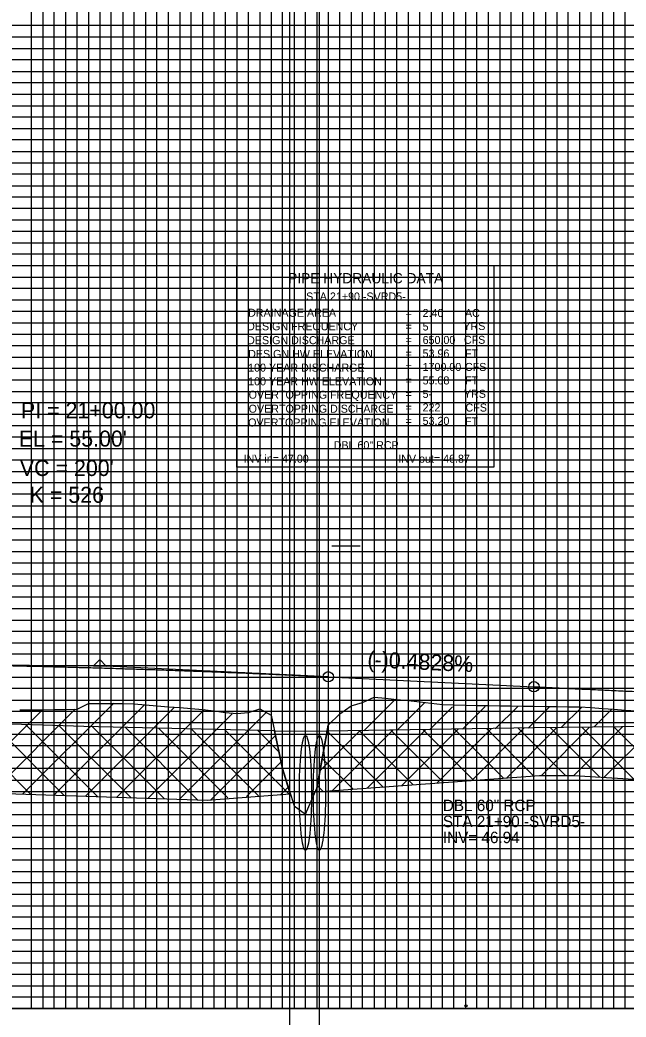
# Model space of a CAD drawing. Extents: x 2345490 to 2445302, y 465165 to 573888.
# Drawn here: x 2382805.1 to 2383070.5, y 491499.3 to 491935.5 of the extents above; entities that cross this region are included whole.
import ezdxf

# ---------------------------------------------------------------- set-up
doc = ezdxf.new("R2010")
doc.units = 0
for name, color, linetype in [('Default', 7, 'Continuous'), ('Old_Level_1', 7, 'Continuous'), ('Old_Level_2', 7, 'Continuous'), ('Old_Level_3', 7, 'Continuous'), ('Old_Level_4', 7, 'Continuous'), ('Old_Level_41', 7, 'Continuous'), ('Old_Level_42', 7, 'Continuous'), ('Old_Level_43', 7, 'Continuous'), ('Old_Level_5', 7, 'Continuous'), ('Old_Level_50', 7, 'Continuous'), ('Old_Level_51', 7, 'Continuous'), ('Old_Level_63', 7, 'Continuous'), ('Prop Vertical Profile Grade', 7, 'Continuous')]:
    doc.layers.add(name, color=color, linetype=linetype)

msp = doc.modelspace()

# ---------------------------------------------------------------- linework, layer by layer
at = {"layer": 'Default'}
msp.add_line((2382916.56515, 491624.43941), (2382939.67785, 491624.39117), dxfattribs=at)
at = {"layer": 'Old_Level_1'}
msp.add_lwpolyline([(2382805.125, 491633.6205), (2382810.125, 491633.6725), (2382815.125, 491633.7245), (2382820.125, 491633.7765), (2382825.125, 491633.8285), (2382830.125, 491633.921), (2382835.125, 491636.42125), (2382840.125, 491636.41825), (2382845.125, 491636.4155), (2382850.125, 491636.4125), (2382855.125, 491636.221), (2382860.125, 491635.8305), (2382865.125, 491635.44025), (2382870.125, 491635.05), (2382875.125, 491634.6595), (2382880.125, 491634.26925), (2382885.125, 491633.879), (2382890.125, 491633.209), (2382895.125, 491632.52625), (2382900.125, 491632.04225), (2382905.125, 491632.4315), (2382910.125, 491634.164), (2382915.125, 491631.2635), (2382920.125, 491608.03925), (2382925.125, 491591.604), (2382930.125, 491588.09825), (2382935.125, 491599.454), (2382940.125, 491626.98825), (2382945.125, 491631.9855), (2382950.125, 491635.42325), (2382955.125, 491636.93325), (2382960.125, 491639.27975), (2382965.125, 491638.7695), (2382970.125, 491638.22925), (2382975.125, 491637.68925), (2382980.125, 491637.149), (2382985.125, 491636.609), (2382990.125, 491636.06875), (2382995.125, 491635.8115), (2383000.125, 491635.71075), (2383005.125, 491635.63575), (2383010.125, 491635.56075), (2383015.125, 491635.48575), (2383020.125, 491635.411), (2383025.125, 491635.336), (2383030.125, 491635.261), (2383035.125, 491635.186), (2383040.125, 491635.11125), (2383045.125, 491635.03625), (2383050.125, 491634.96125), (2383055.125, 491634.6185), (2383060.125, 491634.28925), (2383065.125, 491633.92475), (2383070.125, 491633.55625), (2383075.125, 491633.1875)], dxfattribs=at)
at = {"layer": 'Old_Level_2'}
for p, q in [((2382740.125, 491653.97897), (2382837.37514, 491652.98053)), ((2382840.125, 491655.7023), (2382837.37514, 491652.98053)), ((2382837.37514, 491652.98053), (2382842.8718, 491652.8197)), ((2382842.8718, 491652.8197), (2382840.125, 491655.7023)), ((2382940.125, 491648.12471), (2382842.8718, 491652.8197)), ((2383030.125, 491643.77989), (2383127.3782, 491639.0849))]:
    msp.add_line(p, q, dxfattribs=at)
for centre in [(2382940.125, 491648.12471), (2383030.125, 491643.77989)]:
    msp.add_circle(centre, 2.25, dxfattribs=at)
at = {"layer": 'Old_Level_3'}
msp.add_circle((2383000.34952, 491504.17888), 0.5, dxfattribs=at)
for centre in [(2382930.125, 491597.35225), (2382936.22982, 491597.35225)]:
    msp.add_ellipse(centre, major_axis=(0, 25), ratio=0.106994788, dxfattribs=at)
at = {"layer": 'Old_Level_4'}
for p, q in [((2382900.1285, 491828.06375), (2383012.6285, 491828.06375)), ((2382900.1285, 491753.06375), (2382900.1285, 491828.06375)), ((2383012.6285, 491828.06375), (2383012.6285, 491753.06375)), ((2383012.6285, 491753.06375), (2382900.1285, 491753.06375))]:
    msp.add_line(p, q, dxfattribs=at)
msp.add_lwpolyline([(2382900.1285, 491753.06375), (2383012.6285, 491753.06375), (2383012.6285, 491739.84875), (2382900.1285, 491739.84875)], close=True, dxfattribs=at)
at = {"layer": 'Old_Level_41'}
for p, q in [((2382941.625, 491705.45225), (2382954.125, 491705.45225)), ((2383190.125, 491502.95225), (2381690.125, 491502.95225))]:
    msp.add_line(p, q, dxfattribs=at)
for points in [[(2382815.125, 492527.95225), (2382815.125, 491502.95225), (2382865.125, 491502.95225), (2382865.125, 492527.95225)], [(2382840.125, 492527.95225), (2382840.125, 491502.95225), (2382890.125, 491502.95225), (2382890.125, 492527.95225)], [(2382915.125, 492527.95225), (2382915.125, 491502.95225), (2382965.125, 491502.95225), (2382965.125, 492527.95225)], [(2382940.125, 492527.95225), (2382940.125, 491502.95225), (2382990.125, 491502.95225), (2382990.125, 492527.95225)], [(2383015.125, 492390.40225), (2383015.125, 491502.95225), (2383065.125, 491502.95225), (2383065.125, 492390.40225)], [(2383190.125, 491927.95225), (2381690.125, 491927.95225), (2381690.125, 491877.95225), (2383190.125, 491877.95225)], [(2383190.125, 491852.95225), (2381690.125, 491852.95225), (2381690.125, 491902.95225), (2383190.125, 491902.95225)], [(2383190.125, 491827.95225), (2381690.125, 491827.95225), (2381690.125, 491777.95225), (2383190.125, 491777.95225)], [(2383190.125, 491752.95225), (2381690.125, 491752.95225), (2381690.125, 491802.95225), (2383190.125, 491802.95225)], [(2383190.125, 491727.95225), (2381690.125, 491727.95225), (2381690.125, 491677.95225), (2383190.125, 491677.95225)], [(2383190.125, 491627.95225), (2381690.125, 491627.95225), (2381690.125, 491577.95225), (2383190.125, 491577.95225)], [(2383190.125, 491552.95225), (2381690.125, 491552.95225), (2381690.125, 491602.95225), (2383190.125, 491602.95225)], [(2383190.125, 491527.95225), (2381690.125, 491527.95225)]]:
    msp.add_lwpolyline(points, dxfattribs=at)
at = {"layer": 'Old_Level_42'}
for points in [[(2383040.125, 492390.40225), (2383040.125, 491502.95225), (2383090.125, 491502.95225), (2383090.125, 492390.40225)], [(2383190.125, 491652.95225), (2381690.125, 491652.95225), (2381690.125, 491702.95225), (2383190.125, 491702.95225)]]:
    msp.add_lwpolyline(points, dxfattribs=at)
at = {"layer": 'Old_Level_43'}
for points in [[(2382810.125, 492527.95225), (2382810.125, 491502.95225), (2382820.125, 491502.95225), (2382820.125, 492527.95225)], [(2382825.125, 492527.95225), (2382825.125, 491502.95225), (2382830.125, 491502.95225), (2382830.125, 492527.95225)], [(2382835.125, 492527.95225), (2382835.125, 491502.95225), (2382845.125, 491502.95225), (2382845.125, 492527.95225)], [(2382850.125, 492527.95225), (2382850.125, 491502.95225), (2382855.125, 491502.95225), (2382855.125, 492527.95225)], [(2382860.125, 492527.95225), (2382860.125, 491502.95225), (2382870.125, 491502.95225), (2382870.125, 492527.95225)], [(2382875.125, 492527.95225), (2382875.125, 491502.95225), (2382880.125, 491502.95225), (2382880.125, 492527.95225)], [(2382885.125, 492527.95225), (2382885.125, 491502.95225), (2382895.125, 491502.95225), (2382895.125, 492527.95225)], [(2382900.125, 492527.95225), (2382900.125, 491502.95225), (2382905.125, 491502.95225), (2382905.125, 492527.95225)], [(2382910.125, 492527.95225), (2382910.125, 491502.95225), (2382920.125, 491502.95225), (2382920.125, 492527.95225)], [(2382925.125, 492527.95225), (2382925.125, 491502.95225), (2382930.125, 491502.95225), (2382930.125, 492527.95225)], [(2382935.125, 492527.95225), (2382935.125, 491502.95225), (2382945.125, 491502.95225), (2382945.125, 492527.95225)], [(2382950.125, 492527.95225), (2382950.125, 491502.95225), (2382955.125, 491502.95225), (2382955.125, 492527.95225)], [(2382960.125, 492527.95225), (2382960.125, 491502.95225), (2382970.125, 491502.95225), (2382970.125, 492527.95225)], [(2382975.125, 492527.95225), (2382975.125, 491502.95225), (2382980.125, 491502.95225), (2382980.125, 492527.95225)], [(2382985.125, 492527.95225), (2382985.125, 491502.95225), (2382995.125, 491502.95225), (2382995.125, 492390.40225)], [(2383000.125, 492390.40225), (2383000.125, 491502.95225), (2383005.125, 491502.95225), (2383005.125, 492390.40225)], [(2383010.125, 492390.40225), (2383010.125, 491502.95225), (2383020.125, 491502.95225), (2383020.125, 492390.40225)], [(2383025.125, 492390.40225), (2383025.125, 491502.95225), (2383030.125, 491502.95225), (2383030.125, 492390.40225)], [(2383035.125, 492390.40225), (2383035.125, 491502.95225), (2383045.125, 491502.95225), (2383045.125, 492390.40225)], [(2383050.125, 492390.40225), (2383050.125, 491502.95225), (2383055.125, 491502.95225), (2383055.125, 492390.40225)], [(2383060.125, 492390.40225), (2383060.125, 491502.95225), (2383070.125, 491502.95225), (2383070.125, 492390.40225)], [(2383140.125, 491932.95225), (2381740.125, 491932.95225), (2381740.125, 491922.95225), (2383140.125, 491922.95225)], [(2383140.125, 491917.95225), (2381740.125, 491917.95225), (2381740.125, 491912.95225), (2383140.125, 491912.95225)], [(2383140.125, 491907.95225), (2381740.125, 491907.95225), (2381740.125, 491897.95225), (2383140.125, 491897.95225)], [(2383140.125, 491892.95225), (2381740.125, 491892.95225), (2381740.125, 491887.95225), (2383140.125, 491887.95225)], [(2383140.125, 491882.95225), (2381740.125, 491882.95225), (2381740.125, 491872.95225), (2383140.125, 491872.95225)], [(2383140.125, 491867.95225), (2381740.125, 491867.95225), (2381740.125, 491862.95225), (2383140.125, 491862.95225)], [(2383140.125, 491857.95225), (2381740.125, 491857.95225), (2381740.125, 491847.95225), (2383140.125, 491847.95225)], [(2383140.125, 491842.95225), (2381740.125, 491842.95225), (2381740.125, 491837.95225), (2383140.125, 491837.95225)], [(2383140.125, 491832.95225), (2381740.125, 491832.95225), (2381740.125, 491822.95225), (2383140.125, 491822.95225)], [(2383140.125, 491817.95225), (2381740.125, 491817.95225), (2381740.125, 491812.95225), (2383140.125, 491812.95225)], [(2383140.125, 491807.95225), (2381740.125, 491807.95225), (2381740.125, 491797.95225), (2383140.125, 491797.95225)], [(2383140.125, 491792.95225), (2381740.125, 491792.95225), (2381740.125, 491787.95225), (2383140.125, 491787.95225)], [(2383140.125, 491782.95225), (2381740.125, 491782.95225), (2381740.125, 491772.95225), (2383140.125, 491772.95225)], [(2383140.125, 491767.95225), (2381740.125, 491767.95225), (2381740.125, 491762.95225), (2383140.125, 491762.95225)], [(2383140.125, 491757.95225), (2381740.125, 491757.95225), (2381740.125, 491747.95225), (2383140.125, 491747.95225)], [(2383140.125, 491742.95225), (2381740.125, 491742.95225), (2381740.125, 491737.95225), (2383140.125, 491737.95225)], [(2383140.125, 491732.95225), (2381740.125, 491732.95225), (2381740.125, 491722.95225), (2383140.125, 491722.95225)], [(2383140.125, 491717.95225), (2381740.125, 491717.95225), (2381740.125, 491712.95225), (2383140.125, 491712.95225)], [(2383140.125, 491707.95225), (2381740.125, 491707.95225)], [(2381740.125, 491697.95225), (2383140.125, 491697.95225)], [(2383140.125, 491692.95225), (2381740.125, 491692.95225), (2381740.125, 491687.95225), (2383140.125, 491687.95225)], [(2383140.125, 491682.95225), (2381740.125, 491682.95225)], [(2381740.125, 491672.95225), (2383140.125, 491672.95225)], [(2383140.125, 491667.95225), (2381740.125, 491667.95225), (2381740.125, 491662.95225), (2383140.125, 491662.95225)], [(2383140.125, 491657.95225), (2381740.125, 491657.95225), (2381740.125, 491647.95225), (2383140.125, 491647.95225)], [(2383140.125, 491642.95225), (2381740.125, 491642.95225), (2381740.125, 491637.95225), (2383140.125, 491637.95225)], [(2383140.125, 491632.95225), (2381740.125, 491632.95225), (2381740.125, 491622.95225), (2383140.125, 491622.95225)], [(2383140.125, 491617.95225), (2381740.125, 491617.95225), (2381740.125, 491612.95225), (2383140.125, 491612.95225)], [(2383140.125, 491607.95225), (2381740.125, 491607.95225), (2381740.125, 491597.95225), (2383140.125, 491597.95225)], [(2383140.125, 491592.95225), (2381740.125, 491592.95225), (2381740.125, 491587.95225), (2383140.125, 491587.95225)], [(2383140.125, 491582.95225), (2381740.125, 491582.95225), (2381740.125, 491572.95225), (2383140.125, 491572.95225)], [(2383140.125, 491567.95225), (2381740.125, 491567.95225), (2381740.125, 491562.95225), (2383140.125, 491562.95225)], [(2383140.125, 491557.95225), (2381740.125, 491557.95225), (2381740.125, 491547.95225), (2383140.125, 491547.95225)], [(2383140.125, 491542.95225), (2381740.125, 491542.95225), (2381740.125, 491537.95225), (2383140.125, 491537.95225)], [(2383140.125, 491532.95225), (2381740.125, 491532.95225), (2381740.125, 491522.95225), (2383140.125, 491522.95225)], [(2383140.125, 491517.95225), (2381740.125, 491517.95225), (2381740.125, 491512.95225), (2383140.125, 491512.95225)], [(2383140.125, 491507.95225), (2381740.125, 491507.95225)]]:
    msp.add_lwpolyline(points, dxfattribs=at)
at = {"layer": 'Old_Level_5'}
for p, q in [((2382806.48789, 491596.86685), (2382846.18446, 491636.56342)), ((2382820.17923, 491596.41605), (2382859.63214, 491635.86897)), ((2382955.73571, 491624.46384), (2382969.56194, 491638.29006)), ((2382970.10439, 491624.69038), (2382982.32527, 491636.91126)), ((2382779.10523, 491597.76846), (2382815.0606, 491633.72383)), ((2382792.79656, 491597.31766), (2382829.38624, 491633.90733)), ((2382833.87056, 491595.96525), (2382872.75017, 491634.84486)), ((2382847.56189, 491595.51444), (2382885.86842, 491633.82098)), ((2382861.25322, 491595.06364), (2382898.07201, 491631.88242)), ((2382874.94456, 491594.61284), (2382912.8911, 491632.55938)), ((2382984.47306, 491624.91692), (2382994.4667, 491634.91055)), ((2382998.84174, 491625.14345), (2383008.81912, 491635.12084)), ((2383013.21041, 491625.36999), (2383023.00772, 491635.1673)), ((2383027.57909, 491625.59653), (2383036.94104, 491634.95849)), ((2383042.0097, 491625.88501), (2383050.87437, 491634.74968)), ((2383056.49256, 491626.22574), (2383064.25365, 491633.98682)), ((2382778.49006, 491628.06816), (2382809.80045, 491596.75778)), ((2382793.10152, 491627.59884), (2382824.42408, 491596.27628)), ((2382807.71298, 491627.12952), (2382839.04772, 491595.79478)), ((2382822.32444, 491626.6602), (2382853.67135, 491595.31328)), ((2382943.86165, 491626.73191), (2382943.86165, 491626.73191)), ((2382836.89748, 491626.22929), (2382868.29499, 491594.83178)), ((2382851.36465, 491625.90426), (2382882.91862, 491594.35028)), ((2382865.83181, 491625.57923), (2382896.18742, 491595.22363)), ((2382880.29898, 491625.2542), (2382909.51217, 491596.04101)), ((2382888.58213, 491594.10828), (2382916.98113, 491622.50727)), ((2382894.76615, 491624.92917), (2382922.83693, 491596.85838)), ((2382909.23331, 491624.60414), (2382918.53152, 491615.30593)), ((2382936.53993, 491607.11111), (2382954.04651, 491624.61769)), ((2382939.67785, 491624.39117), (2382964.16024, 491599.90878)), ((2382939.67785, 491624.39117), (2382939.67785, 491624.39117)), ((2382939.67785, 491624.39117), (2382939.67785, 491624.39117)), ((2382941.82671, 491598.25576), (2382968.41517, 491624.84422)), ((2382953.60049, 491624.61066), (2382977.32777, 491600.88338)), ((2382957.09925, 491599.38616), (2382982.78383, 491625.07074)), ((2382967.52313, 491624.83015), (2382990.49531, 491601.85798)), ((2382972.37178, 491600.51656), (2382997.15249, 491625.29727)), ((2382981.44577, 491625.04965), (2383003.66285, 491602.83258)), ((2382987.64432, 491601.64696), (2383011.52115, 491625.52379)), ((2382995.36842, 491625.26914), (2383016.83038, 491603.80718)), ((2383002.91686, 491602.77736), (2383025.88981, 491625.75032)), ((2383009.29106, 491625.48863), (2383029.99792, 491604.78177)), ((2383018.1894, 491603.90776), (2383040.21292, 491625.93129)), ((2383023.2137, 491625.70813), (2383043.94561, 491604.97622)), ((2383033.39998, 491604.97622), (2383054.51507, 491626.0913)), ((2383037.16675, 491625.89721), (2383058.77484, 491604.28912)), ((2383047.54212, 491604.97622), (2383068.81721, 491626.25131)), ((2383051.15242, 491626.05368), (2383073.8457, 491603.3604)), ((2383060.86816, 491604.16012), (2383083.11935, 491626.41131)), ((2383065.13809, 491626.21014), (2383088.91656, 491602.43168)), ((2382904.3397, 491595.72371), (2382919.48644, 491610.87045)), ((2382937.50443, 491612.42245), (2382950.9927, 491598.93418)), ((2382935.331, 491600.45374), (2382937.82516, 491597.95958)), ((2382919.40605, 491596.64792), (2382922.58301, 491599.82488)), ((2382935.12499, 491599.31925), (2382934.83795, 491597.73858))]:
    msp.add_line(p, q, dxfattribs=at)
msp.add_lwpolyline([(2382115.12499, 491640.895), (2382115.12499, 491619.63078), (2382887.1689, 491594.21034), (2382923.4736, 491596.89744), (2382920.12499, 491607.9045), (2382916.56515, 491624.43941), (2382833.04553, 491626.31583), (2382451.93289, 491638.55725), (2382245.12499, 491640.8075)], close=True, dxfattribs=at)
msp.add_lwpolyline([(2382934.83795, 491597.73858), (2383032.62499, 491604.97631), (2383047.62499, 491604.97631), (2383183.48336, 491596.60422), (2383228.76328, 491595.36718), (2383526.4582, 491585.12107), (2383527.68499, 491615.09754), (2383504.06829, 491615.8222), (2383229.77783, 491625.35003), (2383144.70493, 491627.10041), (2383030.41861, 491625.82181), (2382939.67787, 491624.39126), (2382935.12499, 491599.31925)], dxfattribs=at)
at = {"layer": 'Old_Level_50'}
msp.add_lwpolyline([(2384602.625, 492530.50225), (2382936.125, 492530.50225), (2382936.125, 491475.40225), (2384602.625, 491475.40225)], close=True, dxfattribs=at)
at = {"layer": 'Old_Level_51'}
msp.add_lwpolyline([(2384607.125, 492552.95225), (2382923.125, 492552.95225), (2382923.125, 491452.95225), (2384607.125, 491452.95225)], close=True, dxfattribs=at)
at = {"layer": 'Old_Level_63'}
msp.add_line((2381740.125, 491502.95225), (2383587.28325, 491502.95225), dxfattribs=at)
at = {"layer": 'Prop Vertical Profile Grade'}
msp.add_line((2382940.125, 491648.12471), (2383030.125, 491643.77989), dxfattribs=at)
for points in [[(2382740.125, 491653.97897), (2382744.125, 491653.93638), (2382748.125, 491653.89075), (2382752.125, 491653.84208), (2382756.125, 491653.79037), (2382760.125, 491653.73562), (2382764.125, 491653.67783), (2382768.125, 491653.617), (2382772.125, 491653.55313), (2382776.125, 491653.48622), (2382780.125, 491653.41626), (2382784.125, 491653.34327), (2382788.125, 491653.26723), (2382792.125, 491653.18816), (2382796.125, 491653.10604), (2382800.125, 491653.02088), (2382804.125, 491652.93269), (2382808.125, 491652.84145), (2382812.125, 491652.74717), (2382816.125, 491652.64985), (2382820.125, 491652.54949), (2382824.125, 491652.44608), (2382828.125, 491652.33964), (2382832.125, 491652.23016), (2382836.125, 491652.11763), (2382840.125, 491652.00207), (2382844.125, 491651.88346), (2382848.125, 491651.76182), (2382852.125, 491651.63713), (2382856.125, 491651.5094), (2382860.125, 491651.37864), (2382864.125, 491651.24483), (2382868.125, 491651.10798), (2382872.125, 491650.96809), (2382876.125, 491650.82515), (2382880.125, 491650.67918), (2382884.125, 491650.53017), (2382888.125, 491650.37812), (2382892.125, 491650.22302), (2382896.125, 491650.06489), (2382900.125, 491649.90371), (2382904.125, 491649.7395), (2382908.125, 491649.57224), (2382912.125, 491649.40194), (2382916.125, 491649.2286), (2382920.125, 491649.05222), (2382924.125, 491648.8728), (2382928.125, 491648.69034), (2382932.125, 491648.50484), (2382936.125, 491648.3163), (2382940.125, 491648.12471)], [(2383030.125, 491643.77989), (2383034.125, 491643.58732), (2383038.125, 491643.39585), (2383042.125, 491643.20545), (2383046.125, 491643.01614), (2383050.125, 491642.82791), (2383054.125, 491642.64076), (2383058.125, 491642.4547), (2383062.125, 491642.26972), (2383066.125, 491642.08582), (2383070.125, 491641.90301), (2383074.125, 491641.72128), (2383078.125, 491641.54063), (2383082.125, 491641.36107), (2383086.125, 491641.18259), (2383090.125, 491641.00519), (2383094.125, 491640.82888), (2383098.125, 491640.65365), (2383102.125, 491640.4795), (2383106.125, 491640.30643), (2383110.125, 491640.13445), (2383114.125, 491639.96355), (2383118.125, 491639.79374), (2383122.125, 491639.62501), (2383126.125, 491639.45736), (2383130.125, 491639.29079), (2383134.125, 491639.12531), (2383138.125, 491638.96091), (2383142.125, 491638.7976), (2383146.125, 491638.63536), (2383150.125, 491638.47421), (2383154.125, 491638.31415), (2383158.125, 491638.15516), (2383162.125, 491637.99726), (2383166.125, 491637.84045), (2383170.125, 491637.68471), (2383174.125, 491637.53006), (2383178.125, 491637.37649), (2383182.125, 491637.22401), (2383186.125, 491637.07261), (2383190.125, 491636.92229), (2383194.125, 491636.77306), (2383198.125, 491636.6249), (2383202.125, 491636.47784), (2383206.125, 491636.33185), (2383210.125, 491636.18695), (2383214.125, 491636.04313), (2383218.125, 491635.90039), (2383222.125, 491635.75874), (2383226.125, 491635.61817), (2383230.125, 491635.47869)]]:
    msp.add_spline(points, degree=3, dxfattribs=at)

# ---------------------------------------------------------------- texts
at = {"layer": 'Old_Level_2'}
for s, height, p in [('PI = 21+00.00', 7.0000005, (2382805.60137, 491761.18491)), ("EL = 55.00'", 7.0000005, (2382804.64863, 491748.80679)), ("VC = 200'", 7.000001, (2382805.125, 491735.9523)), ('K = 526', 7.000001, (2382809.41231, 491724.22847))]:
    msp.add_text(s, height=height, dxfattribs=at).set_placement(p)
msp.add_text('(-)0.4828%', height=7, rotation=357.2361426, dxfattribs=at).set_placement((2382957.12024, 491652.37091))
at = {"layer": 'Old_Level_3'}
for s, height, p in [('DBL 60" RCP', 4.9999995, (2382990.24623, 491589.35765)), ('STA 21+90 -SVRD5-', 4.9999995, (2382990.24623, 491582.35765)), ('INV= 46.94', 4.999999, (2382990.24623, 491575.35765))]:
    msp.add_text(s, height=height, dxfattribs=at).set_placement(p)
at = {"layer": 'Old_Level_4'}
for s, height, p in [('PIPE HYDRAULIC DATA', 4.49985, (2382922.5285, 491820.23875)), ('STA 21+90 -SVRD5-', 3.4998, (2382930.42225, 491812.7385)), ('DRAINAGE AREA', 3.49995, (2382905.0285, 491805.61375)), ('=        ', 3.49995, (2382973.938, 491805.51375)), ('2.40', 3.49995, (2382981.3985, 491805.51325)), ('AC', 3.49995, (2382999.9535, 491805.51375)), ('DESIGN FREQUENCY', 3.49995, (2382904.5785, 491799.68875)), ('=        ', 3.49995, (2382973.938, 491799.61375)), ('5', 3.49995, (2382981.3985, 491799.6135)), ('YRS', 3.49995, (2382999.2535, 491799.81375)), ('DESIGN DISCHARGE', 3.49995, (2382904.5785, 491793.61375)), ('650.00', 3.49995, (2382981.3985, 491793.7135)), ('CFS', 3.49995, (2382999.4785, 491793.78875)), ('=        ', 3.49995, (2382973.938, 491793.71375)), ('DESIGN HW ELEVATION', 3.49995, (2382905.0285, 491787.61375)), ('=        ', 3.49995, (2382973.938, 491787.81375)), ('53.96', 3.49995, (2382981.3985, 491787.8135)), ('FT', 3.49995, (2382999.9535, 491787.81375)), ('100 YEAR DISCHARGE', 3.49995, (2382905.0285, 491781.61375)), ('=        ', 3.49995, (2382973.938, 491781.91375)), ('1700.00', 3.49995, (2382981.3985, 491781.9135)), ('CFS', 3.49995, (2382999.9535, 491781.91375)), ('100 YEAR HW ELEVATION', 3.49995, (2382905.0285, 491775.61375)), ('55.08', 3.49995, (2382981.3985, 491776.0135)), ('FT', 3.49995, (2382999.9535, 491776.01375)), ('=        ', 3.49995, (2382973.938, 491776.01375)), ('OVERTOPPING FREQUENCY', 3.49995, (2382905.2535, 491769.76375)), ('=        ', 3.49995, (2382973.938, 491770.11375)), ('5-', 3.49995, (2382981.3985, 491770.11375)), ('YRS', 3.49995, (2382999.4785, 491770.16375)), ('OVERTOPPING DISCHARGE', 3.49995, (2382905.2535, 491763.63875)), ('=        ', 3.49995, (2382973.938, 491764.21375)), ('222', 3.49995, (2382981.3985, 491764.21375)), ('CFS', 3.49995, (2383000.1785, 491764.13875)), ('53.20', 3.49995, (2382981.3985, 491758.31375)), ('OVERTOPPING ELEVATION', 3.49995, (2382905.0285, 491757.61375)), ('=        ', 3.49995, (2382973.938, 491758.31375)), ('FT', 3.49995, (2382999.9535, 491758.11375)), ('DBL 60" RCP', 3.4998, (2382942.48325, 491747.6875)), ('INV in= 47.00', 3.4998, (2382903.061, 491741.77575)), ('INV out= 46.87', 3.4998, (2382970.73775, 491741.77575))]:
    msp.add_text(s, height=height, dxfattribs=at).set_placement(p)

doc.saveas('drawing.dxf')
